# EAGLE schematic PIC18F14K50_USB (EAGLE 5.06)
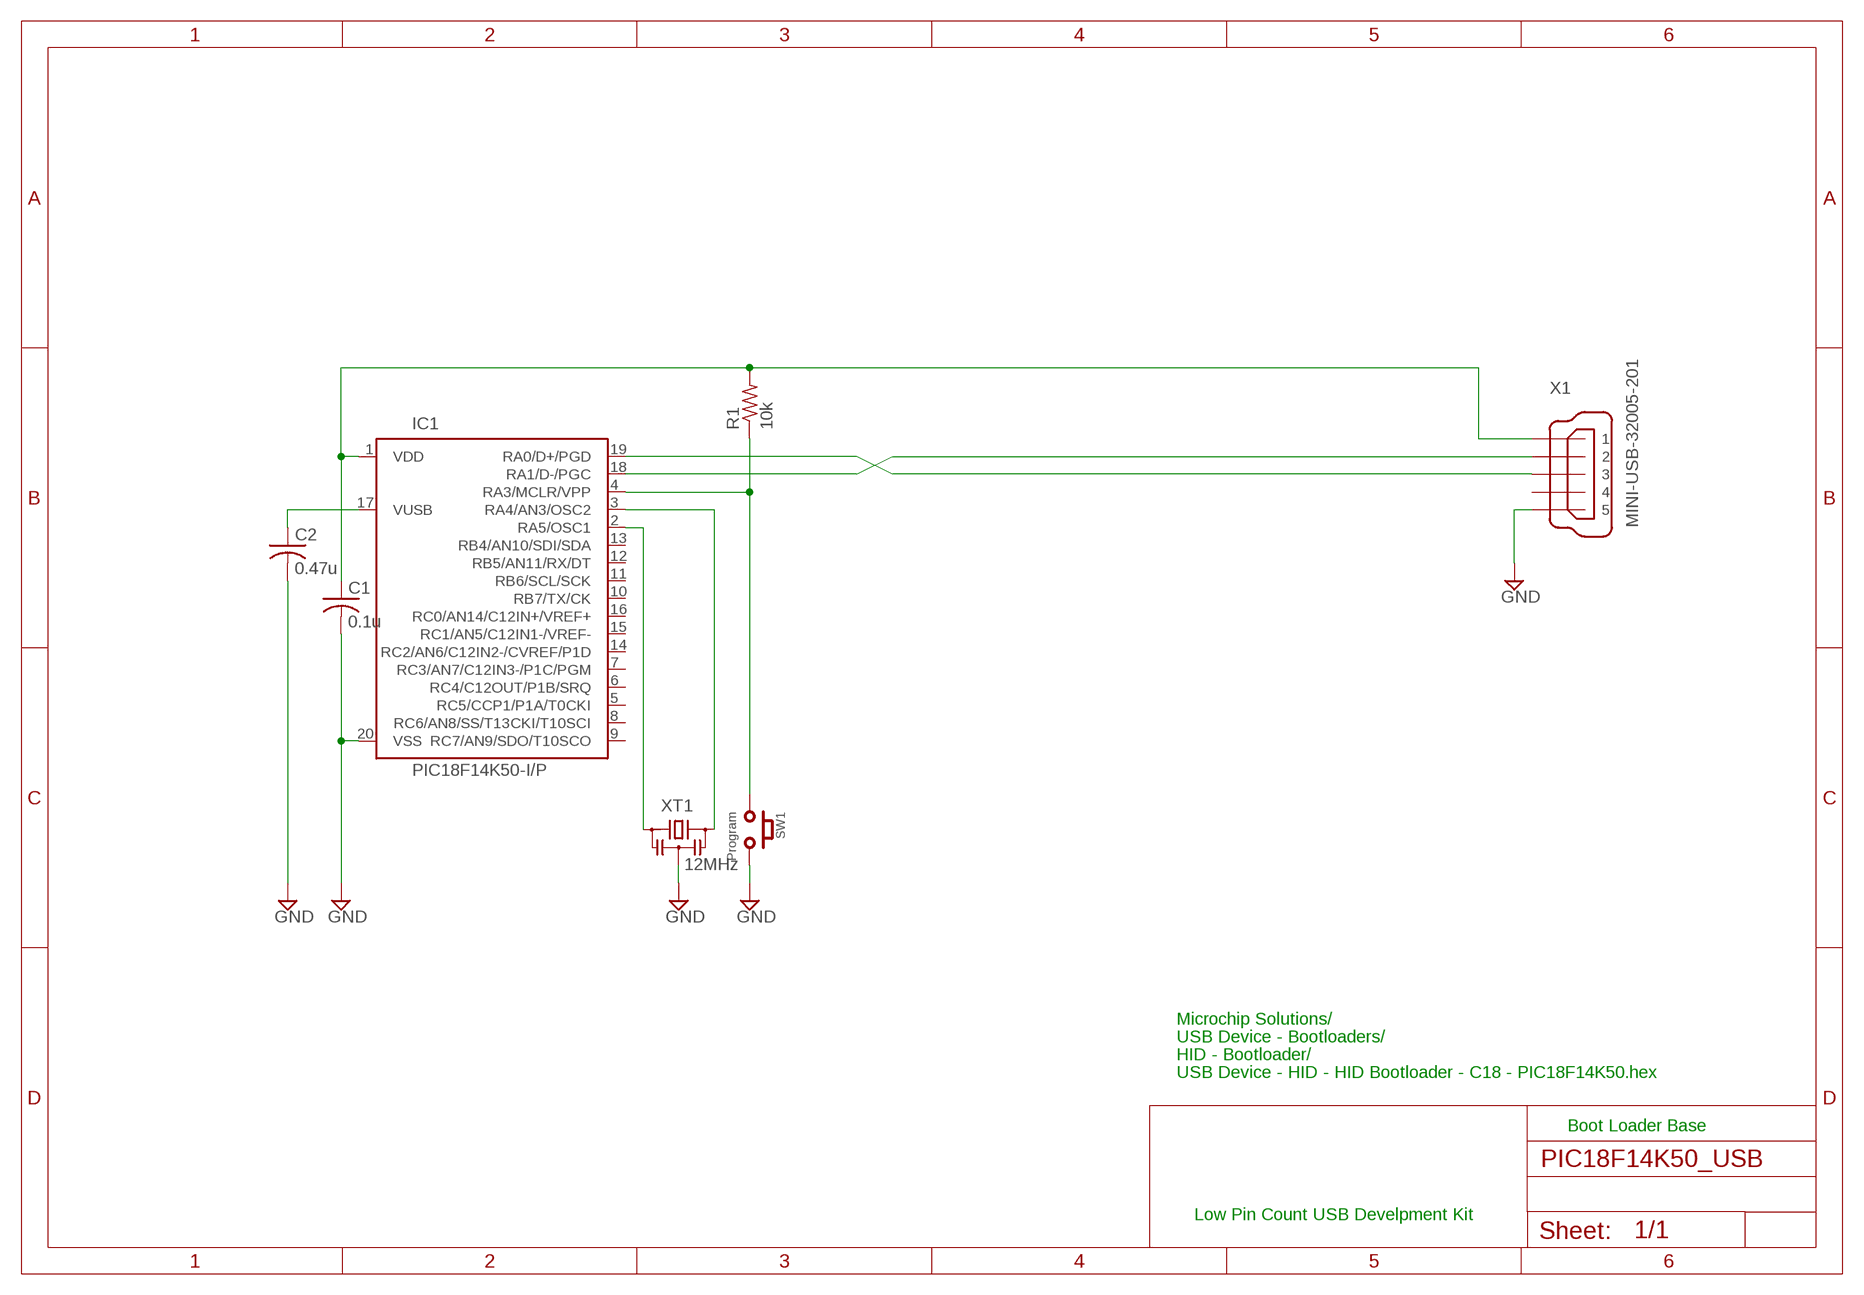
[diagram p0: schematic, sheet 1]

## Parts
C1  0.1u  C-US025-024X044  [C025-024X044]
C2  0.47u  C-US025-024X044  [C025-024X044]
IC1  PIC18F14K50-I/P  [DIL20]
R1  10k  R-US_0204/5  [0204/5]
SW1  Program  SWITCH-PUSH  [SWITCH-PUSH]
X1  MINI-USB-32005-201  [32005-201]
XT1  12MHz  CSTLS  [S3P]

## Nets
GND: C1.2 C2.2 IC1.20(VSS) SW1.P$2(A2) X1.5 XT1.P$2
N$1: IC1.19(RA0/D+/PGD) X1.3
N$3: C1.1 IC1.1(VDD) R1.2 X1.1
N$4: C2.1 IC1.17(VUSB)
N$6: IC1.4(RA3/MCLR/VPP) R1.1 SW1.P$1(A1)
N$13: IC1.2(RA5/OSC1) XT1.P$1
N$14: IC1.3(RA4/AN3/OSC2) XT1.P$3
N$25: IC1.18(RA1/D-/PGC) X1.2
Unconnected: IC1.5(RC5/CCP1/P1A/T0CKI) IC1.6(RC4/C12OUT/P1B/SRQ) IC1.7(RC3/AN7/C12IN3-/P1C/PGM) IC1.8(RC6/AN8/SS/T13CKI/T10SCI) IC1.9(RC7/AN9/SDO/T10SCO) IC1.10(RB7/TX/CK) IC1.11(RB6/SCL/SCK) IC1.12(RB5/AN11/RX/DT) IC1.13(RB4/AN10/SDI/SDA) IC1.14(RC2/AN6/C12IN2-/CVREF/P1D) IC1.15(RC1/AN5/C12IN1-/VREF-) IC1.16(RC0/AN14/C12IN+/VREF+) X1.4

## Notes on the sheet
- Microchip Solutions/
- USB Device - Bootloaders/
- HID - Bootloader/
- USB Device - HID - HID Bootloader - C18 - PIC18F14K50.hex
- Boot Loader Base
- Low Pin Count USB Develpment Kit

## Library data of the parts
C1 C2 = rcl:C-US: CAPACITOR, American symbol
IC1 = TOG:PIC18F14K50
R1 = rcl:R-US_: RESISTOR, American symbol
SW1 = TOG:SWITCH-PUSH
X1 = con-cypressindustries:MINI-USB-: MINI USB-B Conector Source: www.cypressindustries.com
XT1 = TOG:CSTLS: Resonator, Murata Ceralock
